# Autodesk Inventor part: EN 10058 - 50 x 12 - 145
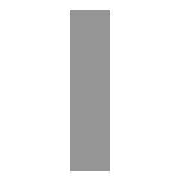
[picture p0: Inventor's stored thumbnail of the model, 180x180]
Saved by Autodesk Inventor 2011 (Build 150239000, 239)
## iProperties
IsCustomPart: 1
_CCFamilyMember: 60
_CCFamilyDisplayName: DIN EN 10058 - Hot rolled flat steel bars for general purposes
_FrameMemberDoc: Frame Member File
_Version: 15.0.0
_GetPNFromCC: 1
Created: 2020-12
Part Number: EN 10058 - 50 x 12 - 145
Material: Steel, Mild
Description: flat steel bar
Document SubType Name: Modeling
Standard: DIN
Designer: PC
Standard Revision: 2004
Standards Organization: DIN
Language: en-US
Size Designation: 50 x 12
Categories: <MemberInstance><Categories><Category DisplayName="Structural Shapes" InternalName="089c4875-fa83-4c05-b084-43b9cc11f5ed" Mnemonic="GRDR"><CategoryParameter Dis
Stock Number: 50 x 12
Density: 7.86 g/cm^3
G_L: 145.000 mm
G_W: 12.000 mm
G_H: 50.000 mm
Author: PC
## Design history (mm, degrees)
node "Start plane"
node "End plane"
sketch "Sketch"
  geometry: L1 (6, -25)-(-6, -25); L2 (-6, -25)-(-6, 25); L3 (-6, 25)-(6, 25); L4 (6, 25)-(6, -25); L5 (-6, 0)-(8, 0); L6 (0, -30)-(0, 40); L7 (0, 54)-(0, -44) reference; L8 (-9.2, 0)-(13.2, 0) reference
  constraints: 12 end point, 2 collinear, 2 parallel, 1 horizontal, 1 perpendicular
  dimensions: "d0" = 50 distance between parallel lines of L3 L1 (= G_W); "d1" = 12 distance between parallel lines of L4 L2 (= G_H); "d4" = 6 distance between parallel lines of L6 L4 (= 0.5 x d1); "d5" = 25 distance between parallel lines of L5 L3 (= 0.5 x d0)
extrude "Body" new body sketch "Sketch" stored distance "d2" = 145 (= G_L); taper "d3" = 0 deg
node "Driven Length"
  sketch "Sketch3"
    geometry: L1 (0, 0)-(10, 0) reference
    constraints: 2 end point, 1 horizontal
  workplane "Work Plane3"
  sketch "Sketch4"
    geometry: L1 (-2, 0)-(12, 0) reference; L2 (-2, 145)-(12, 145) reference
    dimensions: "d9" = 145 distance between parallel lines of L1 L2 (derived)
body "Solid1"
other parameters: "G_W" = 50 [user parameter; used in 1 equation term], "G_H" = 12 [user parameter; used in 1 equation term], "G_L" = 145 (= d9) [user parameter; used in 1 equation term], "G_OFFSET_START" = 0 [user parameter; used in 1 equation term], "G_OFFSET_END" = 0 [user parameter; used in 1 equation term], "d6" = 0 (computed from G_OFFSET_START), "d7" = 145 (= G_OFFSET_END + B_L), "B_L" = 145 [user parameter; used in 1 equation term], "d8" = 90 deg, "MAS" = 0.471 [user parameter]
